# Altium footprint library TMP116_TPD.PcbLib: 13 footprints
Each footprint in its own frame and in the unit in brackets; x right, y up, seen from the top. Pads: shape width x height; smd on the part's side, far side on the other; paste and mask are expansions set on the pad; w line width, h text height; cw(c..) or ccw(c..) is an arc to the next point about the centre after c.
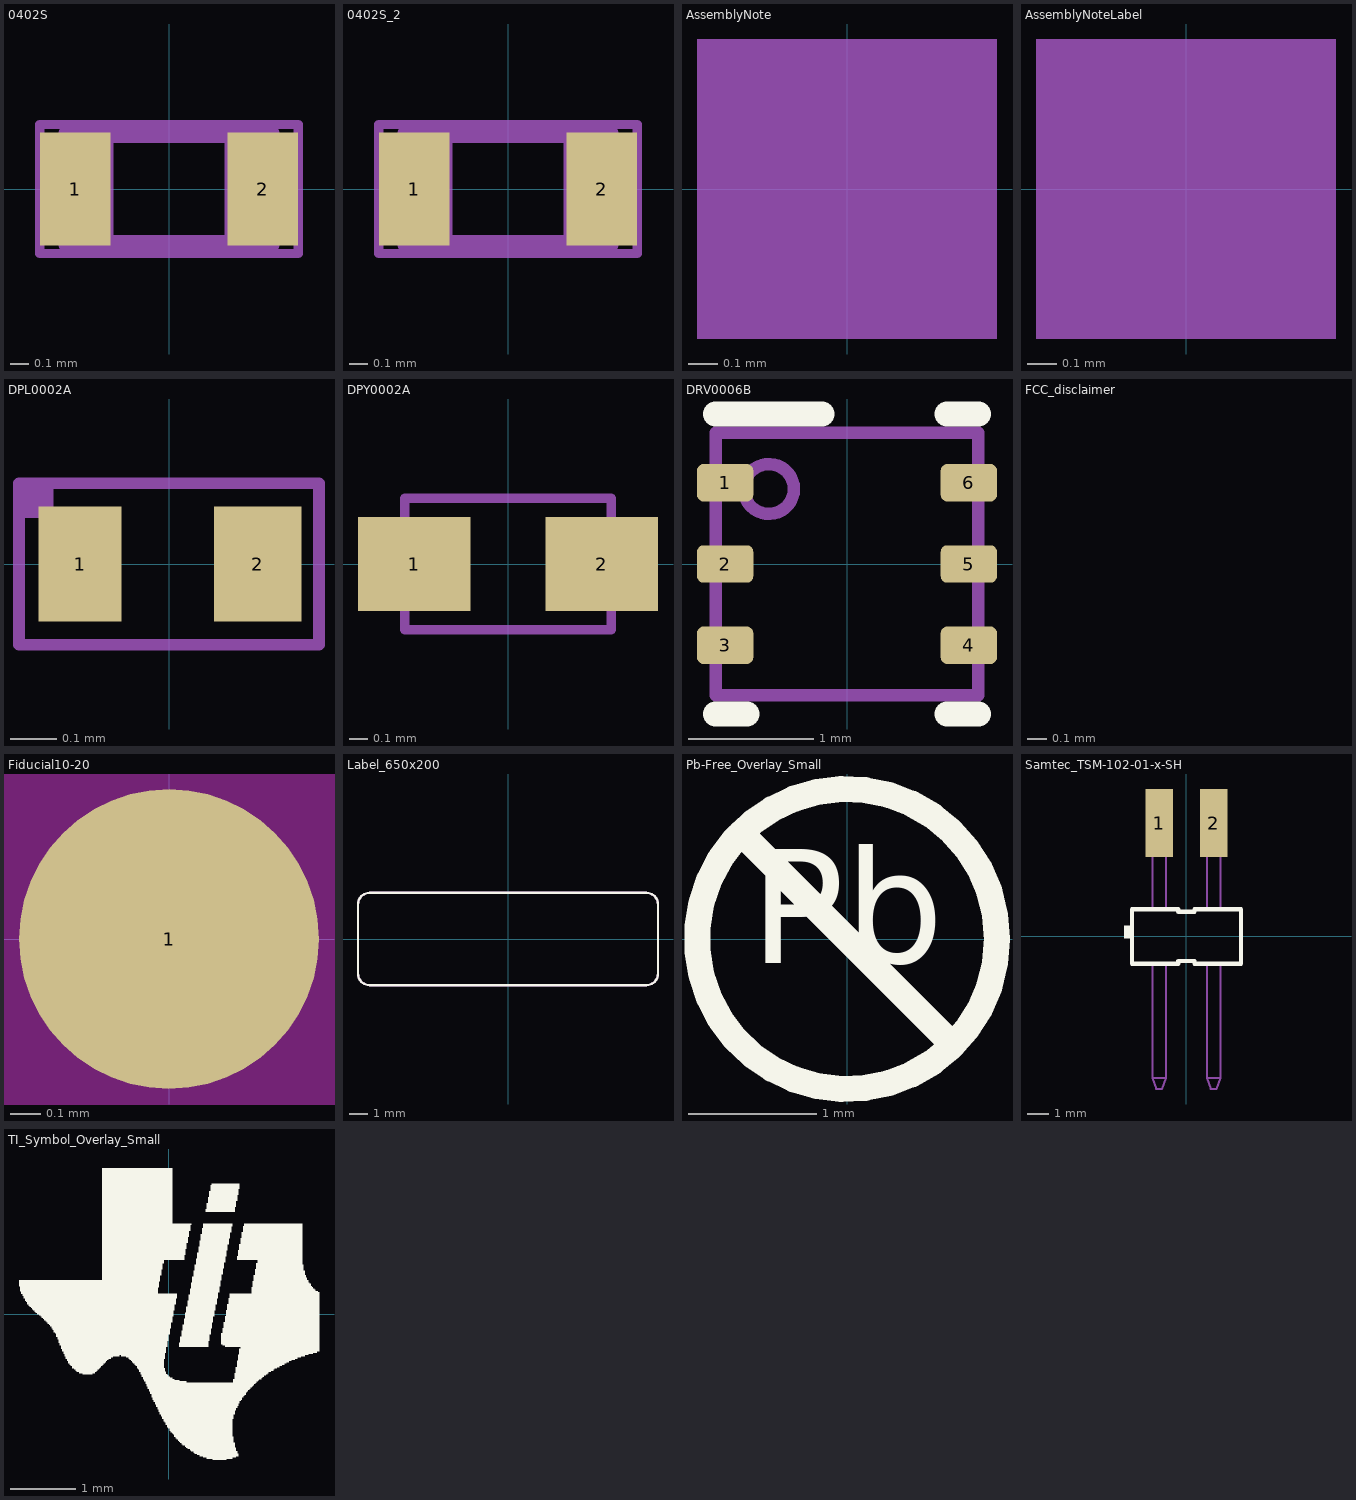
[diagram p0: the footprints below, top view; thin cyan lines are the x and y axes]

## 0402S [mil] "Based on C0402S footprint from PADS legacy"
height 23.62
pads (2):
  rect 15x24 smd: 1(-20,0) 2(20,0)
Mechanical 5:
  lines w1.97: -27.56,-13.78 27.56,-13.78 27.56,13.78 -27.56,13.78 -27.56,-13.78
  text ".Designator" at -21.65,-5.91 h12
Mechanical 13:
  lines w3.94: -13.78,-11.81 -13.78,11.81 ; 13.78,-11.81 13.78,11.81 ; -21.65,-11.81 -21.65,11.81 21.65,11.81 21.65,-11.81 -21.65,-11.81
3D body: height 23.62, standoff 0, extent -21.63,-11.79 -13.8,11.79
3D body: height 23.62, standoff 0, extent -13.76,-11.79 13.76,11.79
3D body: height 23.62, standoff 0, extent 13.8,-11.79 21.63,11.79

## 0402S_2 [mil]
pads (2):
  rect 15x24 smd: 1(-20,0) 2(20,0)
Mechanical 5:
  lines w1.97: -27.56,-13.78 27.56,-13.78 27.56,13.78 -27.56,13.78 -27.56,-13.78
  text ".Designator" at -21.65,-5.91 h12
Mechanical 13:
  lines w3.94: -13.78,-11.81 -13.78,11.81 ; 13.78,-11.81 13.78,11.81 ; -21.65,-11.81 -21.65,11.81 21.65,11.81 21.65,-11.81 -21.65,-11.81
3D body: height 23.62, standoff 0, extent -21.63,-11.79 -13.8,11.79
3D body: height 23.62, standoff 0, extent -13.76,-11.79 13.76,11.79
3D body: height 23.62, standoff 0, extent 13.8,-11.79 21.63,11.79

## AssemblyNote [mm] "Assembly Note"
Mechanical 5:
  rectangle: -0.508,-0.508 0.508,0.508
  text ".Comment" at 1.143,-0.508 h1.02
  text ".Designator" at -4.191,-0.508 h1.02

## AssemblyNoteLabel [mm] "Assembly Note for PCB Labels"
Mechanical 5:
  rectangle: -0.508,-0.508 0.508,0.508
  text ".Designator" at -4.191,-0.508 h1.02
  text "Install label in silkscreened box after final wash.  Text shall be 8 pt font.  Text shall be per the Label Table in the PDF schematic." at 1.143,-0.508 h1.02

## DPL0002A [mm] "R-PX2SON-N2"
height 0.32
pads (2):
  rect 0.18x0.25 smd: 1(-0.193,0)
  rect 0.19x0.25 smd: 2(0.192,0)
Mechanical 5:
  rectangle: -0.325,0.1 -0.25,0.175
  lines w0.025: -0.325,-0.175 -0.325,0.175 0.325,0.175 0.325,-0.175 -0.325,-0.175
  text ".Designator" at -0.279,-0.076 h0.15
3D body: height 0.32, standoff 0, extent -0.324,-0.174 0.324,0.174

## DPY0002A [mm] "R-PX2SON-N2"
height 0.4
pads (2):
  rect 0.6x0.5 smd: 1(-0.5,0) 2(0.5,0)
Mechanical 5:
  lines w0.05: -0.55,-0.35 -0.55,0.35 0.55,0.35 0.55,-0.35 -0.55,-0.35
  text ".Designator" at -0.475,-0.125 h0.25
3D body: height 0.4, standoff 0, extent -0.549,-0.349 0.549,0.349

## DRV0006B [mm] "SON, 6-Leads, Body 2x2mm, Pitch 0.65mm, TI Recommended"
height 0.8
pads (6):
  rrect33% 0.45x0.3 smd: 1(-0.975,0.65) 2(-0.975,0) 3(-0.975,-0.65) 4(0.975,-0.65) 5(0.975,0) 6(0.975,0.65)
Top Overlay:
  lines w0.2: -1.05,-1.2 -0.8,-1.2 ; -1.05,1.2 -0.2,1.2 ; 0.8,-1.2 1.05,-1.2 ; 0.8,1.2 1.05,1.2
Mechanical 5:
  circle w0.1: c-0.625,0.6 r0.2
  lines w0.1: -1.05,-1.05 -1.05,1.05 1.05,1.05 1.05,-1.05 -1.05,-1.05
  text ".Designator" at -0.9,-0.5 h0.51
3D body: height 0.8, standoff 0, extent -1.05,-1.05 1.05,1.05
3D body: height 0.81, standoff 0.5, extent -0.824,0.401 -0.426,0.799

## FCC_disclaimer [mm]
Top Overlay:
  text "For evaluation only; not FCC approved for resale." at -2.388,-87.046 h1.52

## Fiducial10-20 [mm]
pads (1):
  round 1 smd mask+0.5: 1(0,0)
Top Layer keep-out:
  circle w1.178: c0,0 r0.5

## Label_650x200 [mil] "Thermal Transfer Label"
height 1
pads (1):
  round 1 on Mech13: 0(0,0)
Top Overlay:
  lines w5: -325,-75 ccw(c-300,-75) -300,-100 300,-100 ccw(c300,-75) 325,-75 325,75 ccw(c300,75) 300,100 -300,100 ccw(c-300,75) -325,75 -325,-75
Mechanical 5:
  lines w5: -325,-75 ccw(c-300,-75) -300,-100 300,-100 ccw(c300,-75) 325,-75 325,75 ccw(c300,75) 300,100 -300,100 ccw(c-300,75) -325,75 -325,-75
  text ".Designator" at -60,-20 h40
3D body: height 1, standoff 0, extent -325.02,-100.02 325.02,100.02

## Pb-Free_Overlay_Small [mm]
Top Overlay:
  circle w0.203: c0,0 r1.168
  lines w0.203: -0.826,0.826 0.826,-0.826
  text "Pb" at -0.752,-0.48 h1.52

## Samtec_TSM-102-01-x-SH [mm] "Header, 2.54mm, 2x1, R/A, SMT"
height 3.05
pads (2):
  rect 1.27x3.18 smd: 1(-1.27,5.28) 2(1.27,5.28)
Top Overlay:
  rectangle: -2.899,-0.1 -2.599,0.5
  lines w0.2: -2.54,-1.27 -0.381,-1.27 -0.381,-1.143 0.381,-1.143 0.381,-1.27 2.54,-1.27 2.54,1.27 0.381,1.27 0.381,1.143 -0.381,1.143 -0.381,1.27 -2.54,1.27 -2.54,-1.27
Mechanical 5:
  lines w0.1: -1.587,-1.27 -1.587,-6.604 ; -1.587,1.27 -1.587,2.032 -1.587,3.023 -1.587,4.394 -1.587,4.699 -1.587,5.334 ; -0.953,-1.27 -0.953,-6.604 ; -0.953,1.27 -0.953,2.032 -0.953,3.023 -0.953,4.394 -0.953,4.699 -0.953,5.334 ; 0.953,-1.27 0.953,-6.604 ; 0.953,1.27 0.953,2.032 0.953,3.023 0.953,4.394 0.953,4.699 0.953,5.334 ; 1.587,-1.27 1.587,-6.604 ; 1.587,1.27 1.587,2.032 1.587,3.023 1.587,4.394 1.587,4.699 1.587,5.334 ; -1.587,-6.604 -0.953,-6.604 ; -1.587,-6.604 -1.403,-7.112 -1.137,-7.112 -0.953,-6.604 ; -1.587,5.334 -0.953,5.334 ; -1.587,5.334 -1.403,5.842 -1.137,5.842 -0.953,5.334 ; 0.953,-6.604 1.587,-6.604 ; 0.953,-6.604 1.137,-7.112 1.403,-7.112 1.587,-6.604 ; 0.953,5.334 1.587,5.334 ; 0.953,5.334 1.137,5.842 1.403,5.842 1.587,5.334 ; -2.54,-1.27 -2.54,1.27 -0.381,1.27 -0.381,1.143 0.381,1.143 0.381,1.27 2.54,1.27 2.54,-1.27 0.381,-1.27 0.381,-1.143 -0.381,-1.143 -0.381,-1.27 -2.54,-1.27
  text ".Designator" at -1.9,-0.52 h1.85
3D body "Samtec-TSM-102-01-L-SH.stp": height 3.05, standoff 0, extent -2.54,-7.112 2.54,5.842

## TI_Symbol_Overlay_Small [mm]
Top Overlay:
  drawing of 3 lines, arcs and shapes, not listed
